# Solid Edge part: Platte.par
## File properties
Sűrűség: 0,000 kg/m^3
Pontosság: 0,990
Author: bmolnar
Last saved by: bmolnar
Revision: 76
Username: bmolnar
Dokumentum tartalom típus: 0
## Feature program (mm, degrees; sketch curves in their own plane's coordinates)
base feature "unnamed BaseFeature 1"
thread "unnamed Thread 1"
thread "unnamed Thread 2"
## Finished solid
Body 1: solid body, 65 faces, 114 edges, 88 vertices.
  Faces by surface: plane 38, cylinder 12, cone 10, torus 5
  Edges by curve: line 60, circle 36, spline 18
Bounding box of the edges (mm; curved faces can reach further): 45.147 x 47.553 x 10.000, from (-22.5736, -23.7765, 90.5) to (22.5736, 23.7765, 100.5).
Cylindrical faces by radius (mm): R1.5 x2, R1.75 x2, R2.067 x2, R2.75 x2, R3.25 x2, R5 x1, R8.5 x1
Conical faces (half-angle, radius in mm at the cone's reference point): 45 deg R1.85 x2, 45 deg R2.317 x4, 45 deg R8.75 x1, 60 deg R0.7217 x2, 60 deg R1.1547 x1
Toroidal faces (ring radius, tube radius in mm): R1.6 r0.1 x2, R2.45 r0.3 x2, R4.4 r0.6 x1
Planar faces by outward normal: +y 1, +z 7, -y 1, -z 5, oblique 24
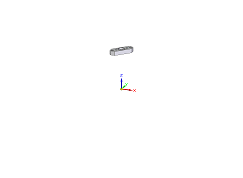
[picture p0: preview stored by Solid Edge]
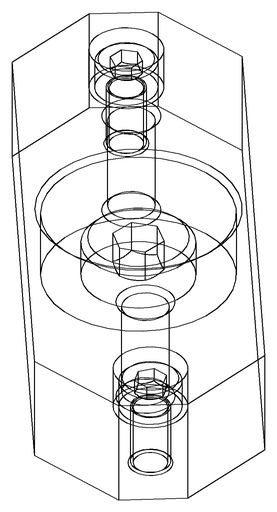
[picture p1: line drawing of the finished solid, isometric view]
